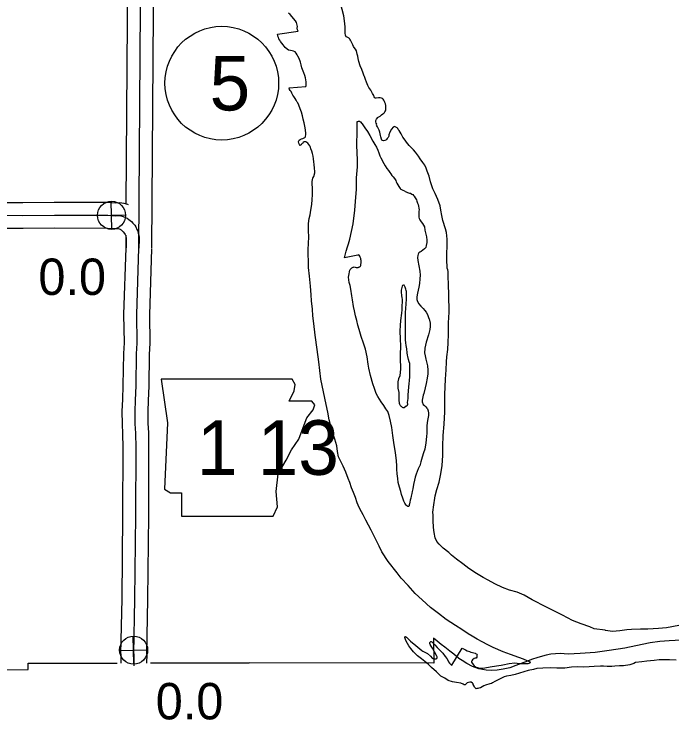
# Model space of a CAD drawing. Extents: x -83719 to 153526, y -11835 to 11446.
# Drawn here: x -32.7 to 221.9, y -44.7 to 228.4 of the extents above; entities that cross this region are included whole.
import ezdxf

# ---------------------------------------------------------------- set-up
doc = ezdxf.new("R2010")
doc.units = 0
for name, color, linetype in [('Level 10', 7, 'Continuous'), ('Level 2', 7, 'Continuous'), ('Level 21', 7, 'Continuous'), ('Level 25', 7, 'Continuous'), ('Level 26', 7, 'Continuous'), ('Level 27', 7, 'Continuous'), ('Level 59', 7, 'Continuous'), ('Level 9', 7, 'Continuous')]:
    doc.layers.add(name, color=color, linetype=linetype)

msp = doc.modelspace()

# ---------------------------------------------------------------- linework, layer by layer
at = {"layer": 'Level 10'}
for points in [[(20.61, 137.73), (21.62, 283.38)], [(10.73, 154.85), (11.59, 278.94)], [(-42.85, 155.52), (-29.27, 155.49)], [(-29.32, 155.49), (-17.14, 155.6), (3.76, 155.57), (6.54, 155.37), (8.24, 155.42), (9.8, 155.16), (11.17, 154.76), (11.48, 154.63)], [(-55.16, 145.55), (-29.29, 145.49)], [(-29.24, 145.49), (-17.1, 145.6), (3.4, 145.57), (6.35, 145.35), (7.57, 145.39), (7.92, 145.29), (8.37, 145.12), (8.52, 145.04), (8.72, 144.9), (9.3, 144.43), (9.55, 144.17), (10.08, 143.52), (10.09, 143.5), (10.25, 143.08), (10.36, 142.87), (10.48, 142.37), (10.62, 141.84), (10.66, 141.53), (10.68, 141.21), (10.61, 137.86)], [(10.61, 137.8), (10.65, 142.87)], [(8.61, -19.11), (9.09, 2.09), (9.42, 34.49), (9.51, 60.57), (9.42, 66.03), (9.22, 69.67), (9.14, 74.69), (9.34, 79.2), (9.55, 84.71), (9.73, 97.08), (9.99, 101.21), (9.79, 112.12), (10.62, 137.92)], [(18.61, -19.33), (19.09, 1.93), (19.42, 34.43), (19.51, 60.63), (19.42, 66.39), (19.22, 70.03), (19.14, 74.55), (19.33, 78.79), (19.55, 84.44), (19.73, 96.7), (19.99, 100.99), (19.79, 112.05), (20.61, 137.6)], [(8.61, -19.19), (8.58, -22.81)], [(18.61, -19.26), (18.58, -22.8)]]:
    msp.add_lwpolyline(points, dxfattribs=at)
at = {"layer": 'Level 2'}
for points in [[(178.66, -19), (175.11, -19.29), (173.26, -19.69), (170.06, -20.6), (167.62, -21.39), (166, -21.94), (163.63, -22.86), (161.53, -23.73), (159.23, -24.55), (156.58, -25.14), (154.29, -25.49), (152.2, -25.62), (150.03, -25.5), (147.18, -25), (144.75, -24.05), (142.48, -22.89), (140.74, -21.75), (139.48, -20.95), (137.56, -19.35), (135.99, -18.1), (133.97, -16.6), (132.63, -15.55), (131.03, -14.27), (129.65, -13.08), (129.78, -22.76), (58.27, -22.62)], [(225.57, -13.94), (220.82, -14.14), (217.26, -14.4), (213.54, -14.86), (207.96, -16.12), (203.69, -16.97), (197.69, -17.88), (192.28, -18.6), (186.46, -19.07), (181.8, -19.23), (178.66, -19)], [(-115.86, -25.74), (-27.26, -25.2), (-27.31, -22.82), (7.25, -22.74)], [(20.15, -22.71), (58.27, -22.62)]]:
    msp.add_lwpolyline(points, dxfattribs=at)
at = {"layer": 'Level 21'}
msp.add_lwpolyline([(24.16, 87.07), (26.7, 70.15), (25.57, 44.49), (27.83, 43.08), (32.06, 43.08), (32.06, 34.06), (67.58, 34.06), (69.27, 37.73), (68.71, 43.65), (69.56, 50.42), (72.66, 55.77), (74.63, 59.72), (77.45, 63.95), (79.14, 68.46), (80.55, 72.13), (83.09, 75.23), (83.65, 77.2), (82.53, 78.61), (73.79, 78.61), (75.76, 82.56), (76.04, 85.1), (74.87, 87.05)], close=True, dxfattribs=at)
at = {"layer": 'Level 26'}
for p, q in [((5.14, 145.08), (4.89, 155.93)), ((-0.41, 150.38), (10.44, 150.63)), ((13.68, -23.17), (13.43, -12.32)), ((8.14, -17.87), (18.98, -17.62))]:
    msp.add_line(p, q, dxfattribs=at)
for centre in [(5.02, 150.51), (13.56, -17.74)]:
    msp.add_circle(centre, 5.43, dxfattribs=at)
at = {"layer": 'Level 27'}
msp.add_circle((47.69, 201.64), 22, dxfattribs=at)
at = {"layer": 'Level 59'}
for points in [[(15.61, 137.76), (16.64, 286.65)], [(-50.16, 150.54), (-29.28, 150.49)], [(-29.28, 150.49), (-17.12, 150.6), (3.58, 150.57), (6.44, 150.36), (7.91, 150.41), (8.67, 150.28), (9.54, 150.02), (10.38, 149.7), (11.05, 149.37), (11.72, 148.91), (12.69, 148.12), (13.29, 147.49), (13.97, 146.66), (14.47, 146.03), (14.85, 145.07), (15.08, 144.57), (15.33, 143.6), (15.53, 142.8), (15.64, 142), (15.68, 141.3), (15.61, 137.76)], [(13.61, -19.22), (14.09, 2.01), (14.42, 34.46), (14.51, 60.6), (14.42, 66.21), (14.22, 69.85), (14.14, 74.62), (14.33, 78.99), (14.55, 84.57), (14.73, 96.89), (14.99, 101.1), (14.79, 112.08), (15.61, 137.76)], [(13.61, -19.22), (13.58, -23.8)]]:
    msp.add_lwpolyline(points, dxfattribs=at)
at = {"layer": 'Level 9'}
for points in [[(108.23, 184.2), (107.93, 184.73), (107.72, 185.19), (107.62, 185.56), (107.65, 185.76), (107.51, 186.16), (107.37, 186.69), (107.34, 187.23), (107.6, 187.73), (108.09, 188.34), (108.16, 188.44), (108.95, 188.84), (109.15, 189.05), (109.45, 189.32), (110.07, 189.76), (110.41, 189.99), (110.64, 190.23), (110.8, 190.53), (111, 190.97), (111.13, 191.27), (111.25, 191.84), (111.25, 192.44), (111.18, 192.97), (111.04, 193.61), (110.97, 193.87), (110.83, 194.2), (110.7, 194.54), (110.42, 195), (110.19, 195.4), (109.85, 195.73), (109.45, 195.89), (108.98, 195.99), (108.35, 195.92), (107.49, 195.77), (107.16, 195.87), (106.95, 196), (106.72, 196.33), (106.48, 196.8), (106.01, 197.7), (105.63, 198.36), (105.33, 198.89), (104.65, 199.92), (104.21, 200.78), (103.67, 202.05), (103.33, 203.01), (102.88, 204.24), (102.85, 204.34), (102.37, 205.54), (101.93, 206.87), (101.28, 208.3), (100.7, 210.03), (100.46, 211.16), (100.31, 212.03), (100.14, 212.9), (99.8, 214.16), (99.42, 214.76), (98.95, 215.39), (98.68, 215.79), (98.38, 216.45), (98.04, 217.25), (97.53, 218.31), (97.26, 218.71), (97.09, 218.88), (96.89, 219.07), (96.69, 219.21), (96.49, 219.24), (96.25, 219.37), (95.78, 219.6), (95.58, 220.16), (95.47, 220.93), (95.46, 222.13), (95.45, 223.27), (95.27, 224.77), (94.98, 227.7), (93.7, 232.56)], [(76.92, 194.31), (76.48, 195.01), (76.07, 195.74), (75.57, 196.5), (75.23, 197.03), (74.99, 197.53), (74.82, 197.79), (74.48, 198.36), (74.18, 198.86), (73.94, 199.19), (73.74, 199.79), (80.19, 200.32), (80.29, 200.79), (80.31, 201.39), (80.31, 202.19), (80.09, 203.69), (79.85, 204.62), (79.44, 205.68), (78.9, 206.91), (78.62, 207.58), (78.38, 208.75), (78.14, 209.71), (77.59, 211.21), (77.18, 212.07), (76.88, 212.57), (76.51, 213.2), (76.07, 213.7), (75.44, 214.03), (74.9, 214.15), (74.24, 214.25), (73.54, 214.44), (73, 214.74), (72.26, 215.43), (71.79, 215.89), (71.39, 216.49), (70.88, 217.15), (70.47, 217.82), (70.17, 218.28), (69.83, 218.81), (69.6, 219.24), (69.49, 219.51), (69.39, 219.84), (69.32, 220.11), (69.28, 220.61), (77.26, 221.72), (76.99, 222.29), (76.92, 222.95), (76.94, 223.55), (76.91, 224.12), (76.6, 225.12), (76.26, 225.72), (75.42, 226.71), (74.98, 227.34), (74.2, 228.24), (73.57, 228.76)], [(100.04, 39.23), (99.48, 41.33), (98.63, 43.32), (97.95, 45.02), (97.23, 47.15), (96.62, 48.65), (95.7, 51.11), (94.71, 53.5), (93.8, 55.26), (92.88, 57.06), (92.46, 59.12), (92.18, 61.29), (91.39, 63.85), (90.67, 66.05), (89.87, 68.91), (89.29, 71.34), (88.72, 74.34), (88.06, 77.34), (86.04, 87.1), (85.28, 93.8), (84.67, 98.57), (83.89, 104.11), (83.28, 108.67), (82.98, 111.64), (82.76, 114.14), (82.43, 117.38), (82.28, 119.71), (81.98, 123.12), (81.61, 126.92), (81.28, 130.29), (81.22, 132.62), (81.16, 135.46), (81.18, 137.5), (81.26, 139.33), (81.33, 142.47), (81.25, 144.21), (81.23, 145.71), (81.29, 147.31), (81.57, 149.25), (81.85, 150.66), (82.2, 152.46), (82.55, 154.67), (82.7, 156.57), (82.81, 158.41), (82.8, 160.05), (82.75, 161.08), (82.67, 162.52), (82.63, 163.42), (82.76, 164.39), (82.98, 164.89), (83.28, 165.56), (83.7, 166.97), (83.69, 167.47), (83.61, 168.74), (83.47, 170.17), (83.36, 171.14), (83.15, 172.3), (83, 173.4), (82.8, 174.37), (82.52, 175.34), (82.21, 176.2), (81.97, 176.87), (81.74, 177.36), (81.4, 177.96), (80.99, 178.39), (80.66, 178.72), (80.36, 178.89), (79.92, 178.92), (79.56, 178.88), (79.23, 178.68), (79.03, 178.47), (78.83, 178.27), (78.6, 177.97), (78.4, 177.77), (78.17, 177.6), (78.01, 177.56), (77.74, 177.86), (77.57, 178.39), (77.43, 178.92), (77.39, 179.09), (77.69, 179.56), (78.02, 179.87), (78.48, 180.07), (79.01, 180.24), (79.58, 180.48), (79.78, 180.58), (79.97, 180.79), (80.07, 180.92), (80.14, 181.19), (80.2, 181.62), (80.19, 182.22), (80.05, 183.62), (79.8, 184.96), (79.56, 186.32), (79.18, 187.69), (78.87, 188.95), (78.49, 190.39), (78.07, 191.72), (77.56, 193.08), (77.12, 193.98), (76.92, 194.31)], [(95.15, 133.99), (95.86, 136.64), (96.35, 138.28), (96.8, 139.49), (97.22, 141.29), (98.56, 147.15), (99.18, 152.49), (99.48, 155.9), (99.86, 160.68), (99.89, 165.02), (100.18, 169.2), (100.16, 171.8), (99.9, 177.64), (99.96, 178.98), (100.1, 181.78), (100.15, 183.32), (100.1, 184.69), (100.13, 185.45), (100.09, 186.76), (100.32, 186.86), (100.65, 186.89), (100.78, 186.93), (100.98, 186.9), (101.35, 186.67), (101.92, 186.07), (102.06, 185.91), (103.07, 184.38), (104.05, 182.96), (104.96, 181.43), (106.15, 179.17), (106.99, 177.84), (107.53, 176.85), (108.04, 175.68), (108.49, 174.69), (108.93, 173.55), (109.2, 172.72), (110.42, 170.6), (110.99, 169.67), (111.57, 168.67), (112.18, 167.84), (112.68, 167.08), (113.12, 166.55), (113.56, 165.95), (114.03, 165.42), (114.5, 164.8), (114.77, 164.4), (115.04, 163.93), (115.25, 163.5), (115.48, 163), (115.82, 162.3), (116.2, 161.64), (116.47, 161.21), (116.73, 160.88), (116.8, 160.78), (117.3, 160.45), (117.74, 160.25), (118.41, 159.93), (118.64, 159.76), (119.01, 159.63), (119.54, 159.37), (119.91, 159.21), (120.31, 159.08), (120.68, 159.01), (121.31, 158.72), (121.62, 158.55), (121.95, 158.12), (122.12, 157.96), (122.59, 157.33), (122.8, 156.93), (123, 156.46), (123.2, 156.03), (123.51, 155.2), (123.68, 154.67), (123.89, 154), (123.96, 153.24), (124.03, 152.64), (124.01, 152.07), (123.98, 151.63), (123.95, 151.27), (123.92, 150.56), (123.92, 150.3), (123.99, 149.73), (124.1, 149.23), (124.3, 148.7), (124.88, 148.04), (125.35, 147.31), (125.79, 146.68), (126.16, 146.05), (126.3, 144.71), (126.96, 142.18), (127.07, 140.85), (127.01, 140.05), (126.86, 138.81), (126.67, 138.07), (126.21, 137.5), (124.88, 136.52), (124.32, 136.31), (123.99, 135.98), (123.66, 135.44), (123.57, 135), (123.51, 134.24)], [(129.38, 35.64), (129.83, 38.45), (130.17, 41.06), (130.33, 41.96), (130.97, 44.44), (131.81, 47.32), (132.54, 50.5), (132.98, 53.7), (133.21, 57.61), (133.28, 61.22), (133.41, 65.26), (133.8, 69.64), (134.05, 74.51), (134.08, 78.39), (134.09, 81.12), (134.27, 87.07), (134.53, 90.68), (134.67, 93.75), (134.82, 95.69), (135.19, 98.56), (135.33, 101.27), (135.43, 104.37), (135.45, 106.34), (135.49, 108.75), (135.61, 111.08), (135.66, 112.85), (135.7, 115.16), (135.64, 117.66), (135.55, 120.3), (135.46, 123.27), (135.41, 124.57), (135.33, 126.1), (135.32, 127.04), (135.32, 127.74), (135.35, 128.11), (135.27, 128.71), (135.13, 129.37), (134.99, 130.04), (134.89, 130.97), (134.77, 132.61), (134.76, 134.14), (134.8, 136.28), (134.89, 137.99), (134.94, 139.52), (134.96, 141.32), (134.84, 142.56), (134.63, 143.89), (134.29, 145.32), (133.26, 148.49), (132.81, 150.42), (132.52, 152.52), (132.21, 154.18), (131.32, 156.61), (130.23, 158.94), (129.42, 160.73), (128.9, 162.26), (128.53, 163.46), (127.91, 165.66), (127.22, 167.59), (126.78, 168.79), (126.24, 169.85), (125.49, 170.94), (124.45, 172.34), (123.81, 173.37), (122.63, 174.89), (121.89, 175.78), (121.08, 176.61), (120.17, 177.54), (119.2, 178.83), (118.66, 179.56), (117.75, 180.75), (117.07, 181.98), (116.7, 182.71), (116.33, 183.31), (116.02, 183.74), (115.79, 184.04), (115.55, 184.34), (115.05, 184.66), (114.55, 184.83), (114.28, 184.72), (114.05, 184.55), (113.39, 183.78), (112.77, 182.64), (112.41, 181.63), (112.29, 181.1), (112.09, 180.66), (111.76, 180.19), (111.43, 179.82), (111.13, 179.62), (110.74, 179.41), (110.34, 179.34), (109.94, 179.41), (109.7, 179.57), (109.53, 179.94), (109.23, 180.9), (109.09, 181.37), (109.02, 181.97), (108.84, 182.63), (108.57, 183.4), (108.47, 183.73), (108.23, 184.2)], [(100.34, 135.08), (95.15, 133.99)], [(115.32, 55.57), (115.07, 57.7), (114.76, 59.47), (114.47, 61.74), (114.19, 63.54), (113.94, 65.37), (113.47, 68.44), (113.02, 70.9), (112.53, 73), (111.95, 74.63), (111.24, 75.66), (110.43, 76.89), (109.32, 78.35), (108.1, 80.34), (107.49, 81.6), (106.74, 83.5), (106.19, 85.26), (105.26, 88.59), (104.67, 91.42), (104.36, 92.89), (104, 95.72), (103.31, 98.72), (102.59, 101.05), (101.7, 103.58), (100.84, 106.27), (100.36, 108.01), (99.91, 109.8), (99.49, 111.6), (99.07, 113.53), (98.69, 115.27), (98.24, 117.77), (98.02, 119.37), (97.6, 121.9), (97.32, 123.3), (96.97, 124.56), (96.72, 126.56), (96.98, 127.84), (97.07, 128.64), (97.3, 129.27), (97.39, 129.54), (97.72, 129.91), (98.09, 130.15), (98.32, 130.29), (98.58, 130.39), (98.65, 130.42), (98.98, 130.53), (99.75, 130.37), (100.31, 130.27), (100.48, 130.31), (100.68, 130.41), (100.91, 130.51), (101.11, 130.61), (101.24, 130.71), (101.41, 130.85), (101.51, 131.12), (101.53, 131.52), (101.6, 132.09), (101.66, 132.59), (101.62, 132.99), (101.55, 133.39), (101.45, 133.82), (101.31, 134.35), (101.11, 134.72), (100.84, 135.05), (100.67, 135.18), (100.34, 135.08)], [(123.51, 134.24), (123.55, 133), (124.39, 128.9), (124.44, 127.37), (124.35, 125.9), (124.17, 124.06), (123.98, 122.76), (123.73, 121.55), (123.4, 120.41), (123.28, 119.68), (123.19, 118.78), (123.23, 117.94), (123.3, 117.51), (123.81, 116.38), (124.75, 115.35), (125.69, 114.39), (126.26, 113.7), (126.8, 112.97), (127.31, 112.07), (127.89, 110.64), (127.96, 110.51), (128.31, 108.74), (128.32, 107.51), (128.16, 106.37), (127.65, 104.2), (126.84, 101.42), (126.33, 99.08), (126.3, 99.01), (126.18, 97.34), (126.39, 96.11), (126.67, 94.91), (126.98, 93.87), (127.33, 92.21), (127.48, 90.64), (127.42, 89.14), (127.17, 87.5), (126.76, 85.43), (126.38, 83.79), (125.86, 81.58), (125.7, 80.98), (125.35, 79.57), (125.22, 79), (125.23, 78.7), (125.26, 78.3), (125.33, 78), (125.47, 77.67), (125.7, 77.37), (126.14, 76.94), (126.71, 76.35), (127.08, 75.95), (127.32, 75.68), (127.49, 75.18), (127.59, 74.82), (127.67, 73.98), (127.71, 73.02), (127.42, 71.71), (127.17, 70.37), (127.08, 68.87), (127.06, 67.47), (127.07, 66.17), (126.99, 64.9), (126.71, 62.49), (126.3, 59.98), (125.81, 58.58), (125.2, 56.9), (124.78, 55.13), (124.3, 53.62), (124.23, 53.39), (123.74, 52.35), (122.89, 50.37), (122.51, 49.16), (122.28, 48.09), (121.9, 46.32), (121.65, 44.71), (121.43, 43.58), (121.2, 42.84), (120.98, 41.9), (120.85, 41.07), (120.66, 40.23), (120.5, 39.46), (120.34, 38.83), (120.28, 38.49), (120.25, 38.16), (120.21, 38.09), (120.08, 37.92), (119.98, 37.85), (119.75, 37.89), (119.35, 38.12), (119.01, 38.38), (118.51, 39.11), (118.2, 39.94), (117.79, 41.04), (117.24, 42.54), (117, 43.7), (116.52, 45.3), (116, 47.13), (115.79, 48.7), (115.54, 50.5), (115.49, 52.23), (115.41, 53.63), (115.32, 55.57)], [(119.02, 76.77), (119.35, 76.84), (119.55, 77.04), (119.71, 77.41), (119.64, 78.05), (119.73, 78.81), (119.79, 79.65), (119.88, 80.92), (120.15, 84.16), (120.2, 85.3), (120.36, 86.57), (120.51, 87.97), (120.53, 89.67), (120.52, 90.77), (120.54, 91.94), (120.5, 92.51), (120.43, 93.14), (120.26, 93.84), (119.95, 94.71), (119.71, 95.87), (119.64, 96.37), (119.39, 97.34), (119.28, 98.84), (119.03, 100.11), (118.89, 101.17), (118.85, 102.38), (118.8, 104.14), (118.82, 105.58), (118.77, 106.98), (118.78, 109.42), (118.83, 110.99), (118.85, 112.92), (118.9, 114.43), (119.08, 116.2), (119.2, 118), (119.22, 119.34), (119.21, 120.21), (119.14, 121.01), (119.03, 121.44), (118.93, 121.97), (118.66, 122.7), (118.45, 123.2), (118.25, 123.5), (117.98, 123.5), (117.65, 123.36), (117.52, 123.13), (117.33, 122.62), (117.1, 121.49), (117.11, 120.79), (117.26, 119.52), (117.4, 118.59), (117.5, 118.02), (117.54, 117.09), (117.43, 115.45), (117.34, 113.95), (117.22, 112.58), (116.91, 109.83), (116.73, 107.93), (116.65, 105.83), (116.78, 102.59), (116.84, 99.99), (116.8, 96.55), (116.76, 94.11), (116.84, 92.44), (116.82, 90.94), (116.74, 89.77), (116.58, 88.37), (116.09, 87.29), (115.8, 86.05), (115.81, 85.55), (115.89, 83.65), (116.21, 81.95), (116.22, 81.08), (116.2, 79.72), (116.24, 78.68), (116.35, 78.11), (116.41, 77.81), (116.48, 77.48), (116.65, 77.15), (116.72, 77.02), (116.89, 76.78), (117.09, 76.62), (117.36, 76.39), (117.53, 76.22), (117.73, 76.12), (117.93, 76.13), (118.19, 76.13), (118.33, 76.16)], [(118.33, 76.16), (119.02, 76.77)], [(144.39, -22.39), (144.95, -23.24), (145.41, -23.82), (146.22, -24.29), (146.66, -24.51), (147.1, -24.63), (147.67, -24.68), (148.74, -24.71), (152.38, -24.12), (154.87, -23.7), (155.89, -23.53), (157.09, -23.32), (158.24, -23.05), (158.94, -22.85), (161.1, -22.68), (162.06, -22.75), (163.4, -22.87), (164.6, -22.86), (165.17, -22.87), (165.93, -22.91), (166.27, -22.9), (166.66, -22.82), (166.96, -22.64), (167.15, -22.5), (167.18, -22.37), (166.81, -22.21), (165.9, -21.81), (164.51, -21.29), (162.63, -20.62), (159.42, -19.46), (156.59, -18.43), (152.76, -16.69), (150.63, -15.63), (148.53, -14.53), (146.59, -13.46), (144.62, -12.36), (143.02, -11.41), (140.57, -9.8), (138.12, -8.14), (134.58, -5.9), (131.53, -3.56), (128.42, -1.27), (125.26, 1.73), (122.51, 4.21), (119.87, 7.26), (117.14, 10.17), (115.54, 12.15), (112.13, 16.57), (109.7, 20.36), (108.6, 22.46), (106.95, 25.81), (105.56, 28.64), (104.46, 30.63), (103.49, 32.57), (102.46, 34.57), (101.79, 35.75), (100.83, 37.42), (100.04, 39.23)], [(224.65, -8.26), (219.81, -9.13), (216.79, -9.34), (212.67, -9.58), (209.77, -9.61), (206.34, -9.7), (204.51, -9.83), (201.76, -10.32), (198.87, -10.46), (196.19, -10.08), (196.09, -10.02), (191.8, -9.43), (190.11, -8.75), (186.84, -7.6), (183.43, -6.28), (179.63, -4.21), (176.24, -2.49), (173.4, -1.08), (167.8, 1.76), (164.71, 3.49), (162.01, 4.74), (159.08, 5.5), (156.31, 6.54), (153.43, 7.95), (150.86, 9.29), (148.85, 10.39), (146.24, 11.87), (143.37, 13.88), (140.98, 15.6), (138.55, 17.52), (136.57, 19.02), (135.54, 19.99), (133.38, 21.78), (131.8, 23.23), (130.96, 24.3), (130.28, 25.78), (129.84, 27.77), (129.64, 29.77), (129.52, 32.4), (129.45, 34.54), (129.38, 35.64)], [(146.44, -32.64), (146.14, -32.65), (145.9, -32.42), (145.52, -32.1), (145.34, -31.71), (145.05, -31.08), (144.94, -30.78), (144.7, -30.46), (144.22, -30.17), (143.66, -30.16), (142.73, -30.39), (142.24, -30.81), (141.89, -31.12), (141.49, -31.2), (141.08, -30.92), (140.27, -30.51), (138.56, -30.24), (137.05, -29.99), (135.37, -29.45), (134.04, -28.59), (132.45, -27.84), (130.76, -26.1), (128.93, -24.42), (127.76, -23.3), (126.29, -22.14), (124.96, -21.12), (123.49, -20), (121.84, -18.42), (120.83, -17.12), (120.09, -16.05), (119.56, -15.2), (118.96, -14.02), (118.66, -13.26), (118.52, -12.83), (118.51, -12.59), (118.74, -12.45), (119.18, -12.67), (120.76, -14.29), (122.75, -15.95), (124.33, -17.2), (125.15, -17.84), (125.53, -18.16), (126.51, -18.6), (127.32, -19.1), (128.45, -20.07), (129.11, -20.84), (129.32, -21), (129.66, -21.09), (129.99, -21.18), (130.26, -21.14), (130.42, -21.1), (130.72, -21.06), (130.92, -20.95), (131.07, -20.61), (131.1, -20.34), (130.81, -19.82), (130.03, -18.38), (129.22, -17.03), (128.73, -16.25), (128.4, -15.59), (128.26, -15.16), (128.28, -14.83), (128.43, -14.52), (128.57, -14.45), (128.73, -14.41), (129, -14.5), (129.55, -14.99), (130.17, -15.67), (131.01, -16.67), (131.66, -17.32), (132.66, -18.22), (133.28, -18.96), (134.15, -20.14), (134.78, -20.95), (135.31, -21.9), (135.46, -22.26), (135.81, -22.75), (136.09, -23.04), (136.36, -23.27), (136.53, -23.39), (136.7, -23.55), (140.71, -16.97), (142, -17.56), (142.71, -17.94), (143.56, -18.31), (144.13, -18.52), (144.8, -18.7), (145.74, -18.97), (145.85, -19.06), (146.35, -19.28), (146.5, -19.54), (146.47, -19.84), (146.41, -20.08), (146.43, -20.41), (146.14, -20.79), (145.78, -20.9), (145.35, -20.99), (144.79, -21.44), (144.44, -21.89), (144.39, -22.19), (144.39, -22.39)], [(223.6, -21.56), (220.97, -21.55), (218.4, -21.47), (216.97, -21.49), (215.07, -21.68), (212.18, -21.98), (210.23, -22.29), (207.84, -22.54), (207.19, -22.96), (205.6, -23.45), (203.22, -23.83), (201.68, -23.85), (199.79, -23.95), (198.63, -24.09), (196.93, -24.05), (195.46, -23.93), (194.23, -23.97), (191.86, -24.12), (189.87, -24.19), (187.87, -24.26), (185.34, -24.21), (183.04, -24.36), (180.49, -24.68), (177.39, -24.66), (175.02, -24.64), (171.96, -24.74), (169.6, -24.89), (168.41, -25.17), (166.23, -25.64), (161.31, -27.11), (159.53, -27.58), (157.94, -27.86), (156.95, -28.07), (155.96, -28.53), (154.13, -29.5), (153.44, -29.92), (152.53, -30.39), (152.1, -30.64), (151.41, -30.8), (149.76, -31.35), (149.17, -31.61), (148.51, -31.96), (147.89, -32.29), (147.23, -32.44), (146.77, -32.52), (146.44, -32.64)]]:
    msp.add_lwpolyline(points, dxfattribs=at)

# ---------------------------------------------------------------- texts
at = {"layer": 'Level 21'}
msp.add_text('1 13', height=21.12, dxfattribs=at).set_placement((38.04, 50.09))
at = {"layer": 'Level 25'}
for p in [(-23.31, 119.7), (22.11, -44.52)]:
    msp.add_text('0.0', height=14.08, dxfattribs=at).set_placement(p)
at = {"layer": 'Level 27'}
msp.add_text('5', height=21.12, dxfattribs=at).set_placement((42.97, 191.08))

doc.saveas('drawing.dxf')
